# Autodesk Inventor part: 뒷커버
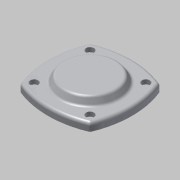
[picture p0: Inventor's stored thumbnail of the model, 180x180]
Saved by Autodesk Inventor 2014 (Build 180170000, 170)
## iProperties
Created: 2013-02
Part Number: 뒷커버
Document SubType Name: Modeling
Designer: 한국산업디자인학원[gmhk.co.kr]
Density: 2.71 g/cm^3
Material: 알루미늄 6061
Mass: 225.473 g
Surface Area: 194.999 cm^2
Volume: 83.2003 cm^3
Appearance: 알루미늄 - 평지
Author: 한국산업디자인학원[gmhk.co.kr]
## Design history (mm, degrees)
sketch "스케치1"
  geometry: C1 r 30 at (0, 0) reference; A1 r 91.05 centre (0, -48.55) between (34.185, 35.839) and (-34.185, 35.839) reference; A2 r 91.05 centre (48.55, 0) between (-35.839, 34.185) and (-35.839, -34.185) reference; A3 r 3 centre (-33.058, 33.058) between (-34.185, 35.839) and (-35.839, 34.185) reference; A4 r 3 centre (33.058, 33.058) between (35.839, 34.185) and (34.185, 35.839) reference; A5 r 91.05 centre (-48.55, 0) between (35.839, -34.185) and (35.839, 34.185) reference; A6 r 3 centre (33.058, -33.058) between (34.185, -35.839) and (35.839, -34.185) reference; A7 r 91.05 centre (0, 48.55) between (-34.185, -35.839) and (34.185, -35.839) reference; A8 r 3 centre (-33.058, -33.058) between (-35.839, -34.185) and (-34.185, -35.839) reference; 1 further point
  node "참조1"
  node "참조2"
  node "참조3"
  node "참조4"
  node "참조5"
  node "참조6"
  node "참조7"
  node "참조8"
  node "참조9"
extrude "돌출1" new body sketch "스케치1" distance "d0" = 8; taper "d1" = 0 deg
sketch "스케치2"
  geometry: C1 r 30 at (0, 0); 1 further point
  constraints: 1 centre point, 1 coincident
  dimensions: "d2" = 60 diameter of C1
extrude "돌출2" join sketch "스케치2" distance "d3" = 7; taper "d4" = -30 deg
sketch "스케치3"
  geometry: C1 r 1.621 at (28.284, 28.284) reference; C2 r 1.621 at (-28.284, 28.284) reference; C3 r 1.621 at (-28.284, -28.284) reference; C4 r 1.621 at (28.284, -28.284) reference; 1 further point
hole "구멍2" sketch "스케치3" at (28.284, 28.284), (28.284, -28.284), (-28.284, -28.284), (-28.284, 28.284) diameter "d14" = 4.5; stored, may be unused: countersink angle "d18" = 90 deg, drill point angle "d20" = 118 deg; dims "d15" = 6, "d16" = 8, "d17" = 4.4, "d19" = 20
extrude "돌출3" join sketch "스케치1" distance "d21" = 12; taper "d22" = 0 deg
hole "구멍3" diameter "d25" = 30; stored, may be unused: countersink angle "d29" = 90 deg, drill point angle "d31" = 0 deg; dims "d23" = 10, "d24" = 10, "d26" = 6, "d27" = 40, "d28" = 12, "d30" = 15
fillet "모깎기1" dims "d32" = 3, "d33" = 0.3
chamfer "모따기1" distance "d34" = 1; stored, may be unused: second distance "d35" = 2, angle "d36" = 45 deg
node "솔리드1"
node "참조10"
node "참조11"
node "참조12"
node "참조13"
